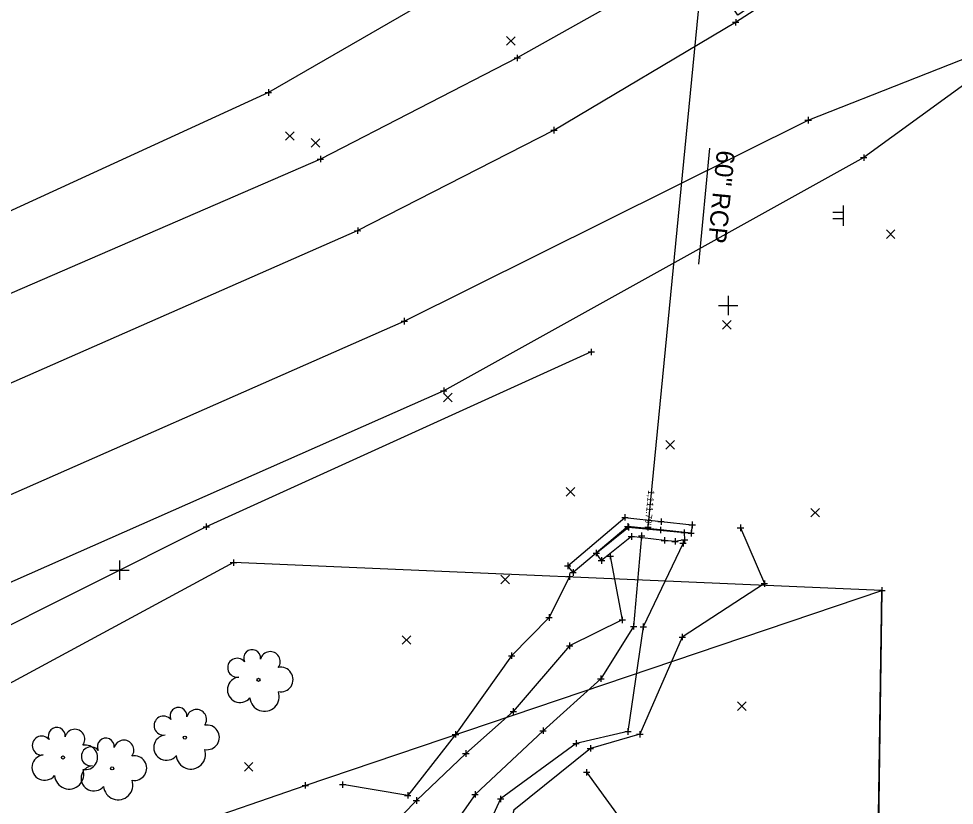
# Model space of a CAD drawing. Extents: x 142461 to 147261, y 511126 to 514697.
# Drawn here: x 144794.9 to 144940.1, y 512851.8 to 512973.9 of the extents above; entities that cross this region are included whole.
import ezdxf

# ---------------------------------------------------------------- set-up
doc = ezdxf.new("R2010")
doc.units = 0
for name, color, linetype in [('DR_X_Ditch', 7, 'Continuous'), ('DR_X_Headwall', 7, 'Continuous'), ('DR_X_Storm_Sewer', 7, 'Continuous'), ('DR_X_Text', 7, 'Continuous'), ('PM_X_Surveyed_Line', 7, 'Continuous'), ('PV_X_EOP', 7, 'Continuous'), ('RD_X_Concrete_Pad', 7, 'Continuous'), ('RD_X_Fence', 7, 'Continuous'), ('SC_Scratch1', 7, 'Continuous'), ('SN_X_Public', 7, 'Continuous'), ('SV_X_Grid', 7, 'Continuous'), ('SV_X_Random_Point', 7, 'Continuous'), ('SV_X_Shot_Marker', 7, 'Continuous'), ('SV_X_Toe_of_Slope', 7, 'Continuous'), ('SV_X_Top_of_Bank', 7, 'Continuous'), ('VG_X_Cells', 7, 'Continuous'), ('VG_X_Tree_Line_Rt', 7, 'Continuous')]:
    doc.layers.add(name, color=color, linetype=linetype)

msp = doc.modelspace()

# ---------------------------------------------------------------- linework, layer by layer
at = {"layer": 'DR_X_Ditch'}
msp.add_lwpolyline([(144891.57, 512893.62), (144890.34, 512879.57), (144885.25, 512871.45), (144876.28, 512863.37), (144865.72, 512853.49), (144856.85, 512840.81), (144851.69, 512835.2), (144860.15, 512816.75), (144870.37, 512801.36), (144880.82, 512788.84)], dxfattribs=at)
at = {"layer": 'DR_X_Headwall'}
msp.add_lwpolyline([(144880.93, 512887.93), (144880.11, 512888.96), (144888.99, 512896.48), (144894.6, 512895.83), (144899.43, 512895.32), (144899.25, 512894.01), (144894.5, 512894.53), (144889.42, 512895.07)], close=True, dxfattribs=at)
at = {"layer": 'DR_X_Storm_Sewer'}
msp.add_line((144902.71, 512999.33), (144892.55, 512894.95), dxfattribs=at)
at = {"layer": 'DR_X_Text'}
msp.add_line((144900.44, 512935.79), (144902.19, 512953.75), dxfattribs=at)
at = {"layer": 'PM_X_Surveyed_Line'}
for points in [[(144161.19, 512623.62), (144234.91, 512664.76), (144308.58, 512704.75), (144382.31, 512742.08), (144431.43, 512764.26), (144460.46, 512777.08), (144499.91, 512794.34), (144547.7, 512814.68), (144592.59, 512833.3), (144667.23, 512864.35), (144709.98, 512882.09), (144731.76, 512891.11), (144777.76, 512910.35), (144847.49, 512940.98), (144877.97, 512956.57), (144906.17, 512973.31), (144970.66, 513014.86), (145008.54, 513039.23), (145047.45, 513063.87), (145126.17, 513113.66), (145208.14, 513166.05), (145269.39, 513204.92)], [(144107.76, 512571.5), (144171, 512608.92), (144233.75, 512643.91), (144295.17, 512677.9), (144371.33, 512718.45), (144406.15, 512735.4), (144436.98, 512749.5), (144470.36, 512764.31), (144526.68, 512788.67), (144607.27, 512822.36), (144672.99, 512849.66), (144737.98, 512876.7), (144783.51, 512895.57), (144854.72, 512926.92), (144917.44, 512958.12), (144951.07, 512971.35), (144954.37, 512973.11)]]:
    msp.add_lwpolyline(points, dxfattribs=at)
at = {"layer": 'PV_X_EOP'}
for p, q in [((144952.49, 512971.53), (144926.06, 512952.3)), ((144926.06, 512952.3), (144860.86, 512916.11)), ((144860.86, 512916.11), (144788.59, 512884.18))]:
    msp.add_line(p, q, dxfattribs=at)
msp.add_lwpolyline([(144911.02, 512977.55), (144906.51, 512974.41), (144900.33, 512983.57), (144872.27, 512967.78), (144841.71, 512952.09), (144773.16, 512922.36), (144725.8, 512902.13), (144705.18, 512893.45), (144708.57, 512885.5), (144665.93, 512867.84), (144590.97, 512836.44), (144546.42, 512818.03), (144498.61, 512797.46), (144459.01, 512780.5), (144429.23, 512767.01), (144423.14, 512777.38)], dxfattribs=at)
at = {"layer": 'RD_X_Concrete_Pad'}
msp.add_lwpolyline([(144898.24, 512893.02), (144896.77, 512892.76), (144895.13, 512892.91), (144889.99, 512893.51), (144885.35, 512889.78), (144884.53, 512890.95), (144889.53, 512894.95), (144898.17, 512894.11)], close=True, dxfattribs=at)
at = {"layer": 'RD_X_Fence'}
msp.add_lwpolyline([(143478.94, 512019.34), (143711.38, 512177.16), (144427.62, 512645.69), (144477.47, 512681.98), (144582.58, 512758.57), (144706.18, 512806.24), (144763.41, 512828.73), (144839.36, 512854.89), (144928.89, 512885.13), (144926.13, 512699.9), (144921.71, 512476.45), (144997.12, 512524.34), (145097.9, 512588.02), (145394.3, 512776.52), (145562.04, 512882.95), (145736.06, 512993.23), (145625.27, 513165.45), (145520.47, 513331.41), (145754.83, 513482.5), (146985.53, 514272.72), (147146.04, 514395.19)], dxfattribs=at)
at = {"layer": 'SN_X_Public'}
for p, q in [((144922.85, 512944.9), (144922.85, 512941.7)), ((144922.85, 512943.78), (144921.25, 512943.78)), ((144922.85, 512942.82), (144921.25, 512942.82)), ((144922.85, 512943.3), (144922.85, 512943.3))]:
    msp.add_line(p, q, dxfattribs=at)
at = {"layer": 'SV_X_Grid'}
for p, q in [((144904.99, 512930.86), (144904.99, 512927.86)), ((144903.49, 512929.36), (144906.49, 512929.36)), ((144904.99, 512929.36), (144904.99, 512929.36)), ((144810.5, 512889.81), (144810.5, 512886.81)), ((144810.51, 512889.81), (144810.51, 512886.81)), ((144809, 512888.31), (144812, 512888.31)), ((144809.01, 512888.31), (144812.01, 512888.31)), ((144810.5, 512888.31), (144810.5, 512888.31)), ((144810.51, 512888.31), (144810.51, 512888.31))]:
    msp.add_line(p, q, dxfattribs=at)
at = {"layer": 'SV_X_Random_Point'}
for p, q in [((144870.59, 512969.75), (144871.94, 512971.07)), ((144870.61, 512971.09), (144871.93, 512969.74)), ((144836.29, 512954.99), (144837.62, 512956.32)), ((144836.29, 512956.32), (144837.62, 512954.99)), ((144840.27, 512953.92), (144841.61, 512955.24)), ((144840.28, 512955.25), (144841.6, 512953.91)), ((144929.57, 512939.74), (144930.91, 512941.08)), ((144929.57, 512941.08), (144930.91, 512939.74)), ((144904.15, 512925.68), (144905.49, 512927.02)), ((144904.15, 512927.02), (144905.49, 512925.68)), ((144860.81, 512914.41), (144862.16, 512915.73)), ((144860.83, 512915.75), (144862.15, 512914.4)), ((144895.35, 512907.07), (144896.68, 512908.41)), ((144895.35, 512908.41), (144896.68, 512907.07)), ((144879.86, 512899.76), (144881.19, 512901.1)), ((144879.86, 512901.1), (144881.19, 512899.76)), ((144917.84, 512896.54), (144919.17, 512897.87)), ((144917.84, 512897.87), (144919.17, 512896.54)), ((144869.74, 512886.17), (144871.08, 512887.51)), ((144869.74, 512887.51), (144871.08, 512886.17)), ((144854.42, 512876.79), (144855.75, 512878.12)), ((144854.42, 512878.12), (144855.75, 512876.79)), ((144906.48, 512866.5), (144907.81, 512867.83)), ((144906.48, 512867.83), (144907.81, 512866.5)), ((144829.91, 512857.12), (144831.24, 512858.45)), ((144829.91, 512858.45), (144831.24, 512857.12))]:
    msp.add_line(p, q, dxfattribs=at)
at = {"layer": 'SV_X_Shot_Marker'}
for p, q in [((144905.67, 512973.32), (144906.67, 512973.31)), ((144906.18, 512973.81), (144906.17, 512972.81)), ((144906.17, 512973.31), (144906.17, 512973.31)), ((144871.77, 512967.79), (144872.77, 512967.78)), ((144872.28, 512968.28), (144872.27, 512967.28)), ((144872.27, 512967.78), (144872.27, 512967.78)), ((144833.63, 512962.92), (144833.63, 512961.92)), ((144833.13, 512962.42), (144834.13, 512962.42)), ((144833.63, 512962.42), (144833.63, 512962.42)), ((144917.44, 512958.62), (144917.43, 512957.62)), ((144877.97, 512957.07), (144877.96, 512956.07)), ((144916.94, 512958.13), (144917.94, 512958.12)), ((144917.44, 512958.12), (144917.44, 512958.12)), ((144877.47, 512956.57), (144878.47, 512956.56)), ((144877.97, 512956.57), (144877.97, 512956.57)), ((144841.71, 512952.59), (144841.7, 512951.59)), ((144926.07, 512952.8), (144926.06, 512951.8)), ((144841.21, 512952.09), (144842.21, 512952.08)), ((144841.71, 512952.09), (144841.71, 512952.09)), ((144925.56, 512952.31), (144926.56, 512952.3)), ((144926.06, 512952.3), (144926.06, 512952.3)), ((144846.99, 512940.98), (144847.99, 512940.97)), ((144847.5, 512941.48), (144847.49, 512940.48)), ((144847.49, 512940.98), (144847.49, 512940.98)), ((144854.22, 512926.93), (144855.22, 512926.92)), ((144854.73, 512927.42), (144854.72, 512926.42)), ((144854.72, 512926.92), (144854.72, 512926.92)), ((144883.26, 512922.15), (144884.26, 512922.15)), ((144883.76, 512922.65), (144883.76, 512921.65)), ((144883.76, 512922.15), (144883.76, 512922.15)), ((144860.87, 512916.61), (144860.86, 512915.61)), ((144860.36, 512916.12), (144861.36, 512916.11)), ((144860.86, 512916.11), (144860.86, 512916.11)), ((144888.49, 512896.48), (144889.49, 512896.48)), ((144888.99, 512896.98), (144888.99, 512895.98)), ((144888.99, 512896.48), (144888.99, 512896.48)), ((144894.6, 512896.33), (144894.6, 512895.33)), ((144823.49, 512895.03), (144824.49, 512895.03)), ((144823.99, 512895.53), (144823.99, 512894.53)), ((144823.99, 512895.03), (144823.99, 512895.03)), ((144888.92, 512895.07), (144889.92, 512895.07)), ((144889.03, 512894.95), (144890.03, 512894.95)), ((144889.42, 512895.57), (144889.42, 512894.57)), ((144889.42, 512895.07), (144889.42, 512895.07)), ((144889.53, 512895.45), (144889.53, 512894.45)), ((144889.53, 512894.95), (144889.53, 512894.95)), ((144892.05, 512894.95), (144893.05, 512894.95)), ((144892.55, 512895.45), (144892.55, 512894.45)), ((144892.55, 512894.95), (144892.55, 512894.95)), ((144894, 512894.53), (144895, 512894.53)), ((144894.1, 512895.83), (144895.1, 512895.83)), ((144894.5, 512895.03), (144894.5, 512894.03)), ((144894.5, 512894.53), (144894.5, 512894.53)), ((144894.6, 512895.83), (144894.6, 512895.83)), ((144898.17, 512894.61), (144898.17, 512893.61)), ((144898.93, 512895.32), (144899.93, 512895.32)), ((144899.25, 512894.51), (144899.25, 512893.51)), ((144899.43, 512895.82), (144899.43, 512894.82)), ((144899.43, 512895.32), (144899.43, 512895.32)), ((144906.43, 512894.85), (144907.43, 512894.85)), ((144906.93, 512895.35), (144906.93, 512894.35)), ((144906.93, 512894.85), (144906.93, 512894.85)), ((144889.49, 512893.51), (144890.49, 512893.51)), ((144889.99, 512894.01), (144889.99, 512893.01)), ((144889.99, 512893.51), (144889.99, 512893.51)), ((144891.07, 512893.62), (144892.07, 512893.62)), ((144891.57, 512894.12), (144891.57, 512893.12)), ((144891.57, 512893.62), (144891.57, 512893.62)), ((144895.13, 512893.41), (144895.13, 512892.41)), ((144896.77, 512893.26), (144896.77, 512892.26)), ((144897.67, 512894.11), (144898.67, 512894.11)), ((144897.74, 512893.02), (144898.74, 512893.02)), ((144898, 512892.97), (144898, 512891.97)), ((144898.17, 512894.11), (144898.17, 512894.11)), ((144898.24, 512893.52), (144898.24, 512892.52)), ((144898.24, 512893.02), (144898.24, 512893.02)), ((144898.75, 512894.01), (144899.75, 512894.01)), ((144899.25, 512894.01), (144899.25, 512894.01)), ((144894.63, 512892.91), (144895.63, 512892.91)), ((144895.13, 512892.91), (144895.13, 512892.91)), ((144896.27, 512892.76), (144897.27, 512892.76)), ((144896.77, 512892.76), (144896.77, 512892.76)), ((144897.5, 512892.47), (144898.5, 512892.47)), ((144898, 512892.47), (144898, 512892.47)), ((144884.03, 512890.95), (144885.03, 512890.95)), ((144884.53, 512891.45), (144884.53, 512890.45)), ((144884.53, 512890.95), (144884.53, 512890.95)), ((144885.35, 512890.28), (144885.35, 512889.28)), ((144886.21, 512890.47), (144887.21, 512890.47)), ((144886.71, 512890.97), (144886.71, 512889.97)), ((144886.71, 512890.47), (144886.71, 512890.47)), ((144827.72, 512889.47), (144828.72, 512889.46)), ((144828.23, 512889.96), (144828.22, 512888.96)), ((144828.22, 512889.46), (144828.22, 512889.46)), ((144879.61, 512888.96), (144880.61, 512888.96)), ((144880.11, 512889.46), (144880.11, 512888.46)), ((144880.11, 512888.96), (144880.11, 512888.96)), ((144884.85, 512889.78), (144885.85, 512889.78)), ((144885.35, 512889.78), (144885.35, 512889.78)), ((144879.9, 512887.28), (144880.9, 512887.28)), ((144880.4, 512887.78), (144880.4, 512886.78)), ((144880.4, 512887.28), (144880.4, 512887.28)), ((144880.43, 512887.93), (144881.43, 512887.93)), ((144880.93, 512888.43), (144880.93, 512887.43)), ((144880.93, 512887.93), (144880.93, 512887.93)), ((144910.13, 512886.2), (144911.13, 512886.2)), ((144910.63, 512886.7), (144910.63, 512885.7)), ((144910.63, 512886.2), (144910.63, 512886.2)), ((144928.39, 512885.13), (144929.39, 512885.12)), ((144928.39, 512885.13), (144929.39, 512885.12)), ((144928.89, 512885.63), (144928.88, 512884.63)), ((144928.89, 512885.63), (144928.88, 512884.63)), ((144928.89, 512885.13), (144928.89, 512885.13)), ((144928.89, 512885.13), (144928.89, 512885.13)), ((144877.21, 512881.45), (144877.21, 512880.45)), ((144876.71, 512880.95), (144877.71, 512880.95)), ((144877.21, 512880.95), (144877.21, 512880.95)), ((144888.08, 512880.56), (144889.08, 512880.56)), ((144888.58, 512881.06), (144888.58, 512880.06)), ((144888.58, 512880.56), (144888.58, 512880.56)), ((144890.34, 512880.07), (144890.34, 512879.07)), ((144891.83, 512879.99), (144891.83, 512878.99)), ((144889.84, 512879.57), (144890.84, 512879.57)), ((144890.34, 512879.57), (144890.34, 512879.57)), ((144891.33, 512879.49), (144892.33, 512879.49)), ((144891.83, 512879.49), (144891.83, 512879.49)), ((144880.39, 512877.05), (144880.39, 512876.05)), ((144897.39, 512877.9), (144898.39, 512877.9)), ((144897.89, 512878.4), (144897.89, 512877.4)), ((144897.89, 512877.9), (144897.89, 512877.9)), ((144879.89, 512876.55), (144880.89, 512876.55)), ((144880.39, 512876.55), (144880.39, 512876.55)), ((144870.89, 512875.01), (144871.89, 512875.01)), ((144871.39, 512875.51), (144871.39, 512874.51)), ((144871.39, 512875.01), (144871.39, 512875.01)), ((144884.75, 512871.45), (144885.75, 512871.45)), ((144885.25, 512871.95), (144885.25, 512870.95)), ((144885.25, 512871.45), (144885.25, 512871.45)), ((144871.65, 512866.85), (144871.65, 512865.85)), ((144871.15, 512866.35), (144872.15, 512866.35)), ((144871.65, 512866.35), (144871.65, 512866.35)), ((144862.18, 512862.81), (144863.18, 512862.81)), ((144862.68, 512863.31), (144862.68, 512862.31)), ((144862.68, 512862.81), (144862.68, 512862.81)), ((144875.78, 512863.37), (144876.78, 512863.37)), ((144876.28, 512863.87), (144876.28, 512862.87)), ((144876.28, 512863.37), (144876.28, 512863.37)), ((144888.96, 512863.25), (144889.96, 512863.25)), ((144889.46, 512863.75), (144889.46, 512862.75)), ((144889.46, 512863.25), (144889.46, 512863.25)), ((144890.8, 512862.82), (144891.8, 512862.82)), ((144891.3, 512863.32), (144891.3, 512862.32)), ((144891.3, 512862.82), (144891.3, 512862.82)), ((144880.9, 512861.4), (144881.9, 512861.4)), ((144881.4, 512861.9), (144881.4, 512860.9)), ((144881.4, 512861.4), (144881.4, 512861.4)), ((144883.62, 512861.13), (144883.62, 512860.13)), ((144863.78, 512859.83), (144864.78, 512859.83)), ((144864.28, 512860.33), (144864.28, 512859.33)), ((144864.28, 512859.83), (144864.28, 512859.83)), ((144883.12, 512860.63), (144884.12, 512860.63)), ((144883.62, 512860.63), (144883.62, 512860.63)), ((144882.54, 512856.92), (144883.54, 512856.92)), ((144883.04, 512857.42), (144883.04, 512856.42)), ((144883.04, 512856.92), (144883.04, 512856.92)), ((144839.36, 512855.39), (144839.35, 512854.39)), ((144845.16, 512855.51), (144845.16, 512854.51)), ((144838.86, 512854.89), (144839.86, 512854.88)), ((144839.36, 512854.89), (144839.36, 512854.89)), ((144844.66, 512855.01), (144845.66, 512855.01)), ((144845.16, 512855.01), (144845.16, 512855.01)), ((144855.27, 512853.84), (144855.27, 512852.84)), ((144865.72, 512853.99), (144865.72, 512852.99)), ((144854.77, 512853.34), (144855.77, 512853.34)), ((144855.27, 512853.34), (144855.27, 512853.34)), ((144856.11, 512852.54), (144857.11, 512852.54)), ((144856.61, 512853.04), (144856.61, 512852.04)), ((144856.61, 512852.54), (144856.61, 512852.54)), ((144865.22, 512853.49), (144866.22, 512853.49)), ((144865.72, 512853.49), (144865.72, 512853.49)), ((144869.19, 512852.78), (144870.19, 512852.78)), ((144869.69, 512853.28), (144869.69, 512852.28)), ((144869.69, 512852.78), (144869.69, 512852.78))]:
    msp.add_line(p, q, dxfattribs=at)
at = {"layer": 'SV_X_Toe_of_Slope'}
for points in [[(145536.33, 513468.51), (145487.34, 513431.87), (145445.96, 513398.71), (145400.54, 513359.53), (145354.59, 513321.64), (145305.79, 513280.24), (145266.24, 513246.77), (145228.58, 513220.65), (145175.08, 513189.66), (145126.31, 513155.94), (145081.98, 513127.67), (145034.97, 513097.1), (144983.36, 513063.49), (144934.41, 513028.84), (144889.77, 512994.77), (144833.63, 512962.42), (144772.97, 512934.59), (144716.73, 512910.04), (144663.56, 512886.77), (144614.86, 512866.63), (144547.92, 512838.93)], [(144898, 512892.47), (144891.83, 512879.49), (144889.46, 512863.25), (144881.4, 512861.4), (144869.69, 512852.78), (144864.6, 512841.71), (144859.83, 512834.13), (144865.32, 512819.69), (144872.78, 512803.57), (144882.57, 512791.97)], [(144886.71, 512890.47), (144888.58, 512880.56), (144880.39, 512876.55), (144871.65, 512866.35), (144864.28, 512859.83), (144856.61, 512852.54), (144850.44, 512846.16), (144844.67, 512837.97), (144847.86, 512828.76), (144854.85, 512821.69), (144866.46, 512797.57), (144878.13, 512787.03)]]:
    msp.add_lwpolyline(points, dxfattribs=at)
at = {"layer": 'SV_X_Top_of_Bank'}
for points in [[(144883.76, 512922.15), (144823.99, 512895.03), (144787.2, 512876.59)], [(144906.93, 512894.85), (144910.63, 512886.2), (144897.89, 512877.9), (144891.3, 512862.82), (144883.62, 512860.63), (144871.74, 512851.06), (144868.97, 512840.7), (144865.16, 512834.06), (144871.35, 512825.18), (144881.67, 512812.01)], [(144880.4, 512887.28), (144877.21, 512880.95), (144871.39, 512875.01), (144862.68, 512862.81), (144855.27, 512853.34), (144845.16, 512855.01)], [(144883.04, 512856.92), (144896.67, 512838.13), (144907.22, 512815.75), (144914.01, 512790.33), (144917.19, 512767.79), (144912.1, 512749.4), (144908.01, 512729.81), (144913.67, 512687.02), (144921.48, 512648.83)]]:
    msp.add_lwpolyline(points, dxfattribs=at)
at = {"layer": 'VG_X_Cells'}
for centre in [(144832.09, 512871.27), (144820.66, 512862.3), (144801.75, 512859.21), (144809.38, 512857.53)]:
    msp.add_circle(centre, 0.24, dxfattribs=at)
for centre, radius, start, end in [((144831.11, 512874.64), 1.32, 354.0047, 205.9741), ((144833.92, 512874.1), 1.55, 323.83, 165.0376), ((144828.78, 512873.14), 1.47, 39.0625, 279.5412), ((144835.55, 512871.31), 1.91, 259.1453, 101.4596), ((144829.24, 512869.72), 1.97, 96.1722, 320.5737), ((144833.04, 512868.67), 2.28, 184.9476, 19.4572), ((144819.67, 512865.67), 1.32, 354.0047, 205.9741), ((144817.35, 512864.17), 1.47, 39.0625, 279.5412), ((144822.48, 512865.13), 1.55, 323.83, 165.0376), ((144824.12, 512862.34), 1.91, 259.1453, 101.4596), ((144798.44, 512861.07), 1.47, 39.0625, 279.5412), ((144800.77, 512862.57), 1.32, 354.0047, 205.9741), ((144803.58, 512862.04), 1.55, 323.83, 165.0376), ((144817.8, 512860.75), 1.97, 96.1722, 320.5737), ((144805.21, 512859.24), 1.91, 259.1453, 101.4596), ((144808.39, 512860.9), 1.32, 354.0047, 205.9741), ((144811.2, 512860.36), 1.55, 323.83, 165.0376), ((144798.9, 512857.66), 1.97, 96.1722, 320.5737), ((144806.07, 512859.4), 1.47, 39.0625, 279.5412), ((144821.6, 512859.7), 2.28, 184.9476, 19.4572), ((144812.84, 512857.57), 1.91, 259.1453, 101.4596), ((144802.7, 512856.6), 2.28, 184.9476, 19.4572), ((144806.52, 512855.99), 1.97, 96.1722, 320.5737), ((144810.32, 512854.93), 2.28, 184.9476, 19.4572)]:
    msp.add_arc(centre, radius, start, end, dxfattribs=at)
at = {"layer": 'VG_X_Tree_Line_Rt'}
msp.add_lwpolyline([(144921.71, 512476.45), (144926.13, 512699.9), (144928.89, 512885.13), (144828.22, 512889.46), (144750.74, 512847.64), (144698.78, 512825.75), (144584.26, 512777), (144464.04, 512719.97), (144375.77, 512695.09), (143711.38, 512177.16), (143478.94, 512019.34)], dxfattribs=at)

# ---------------------------------------------------------------- texts
at = {"layer": 'DR_X_Text'}
msp.add_text('60" RCP', height=2.8, rotation=264.4414, dxfattribs=at).set_placement((144903.28, 512953.53))
at = {"layer": 'SC_Scratch1'}
msp.add_text("1,111.79'", height=1, rotation=264.4414, dxfattribs=at).set_placement((144892.61, 512900.75))

doc.saveas('drawing.dxf')
